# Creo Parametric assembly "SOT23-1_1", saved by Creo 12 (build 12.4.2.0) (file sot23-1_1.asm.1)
Units: Custom; MM, KILOGRAM, SECS

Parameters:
  PTC_WM_ITERATION = "0"
  PTC_WM_VERSION = "-.0"
  PTC_WM_LIFECYCLE_STATE = "In Work"
  PTC_WM_LIFECYCLE = "MO_CADDocument"
  PTC_WM_CREATED_BY = "Maximilian Roepper (Z0017RMS: MO)"
  PTC_WM_CREATED_ON = "18-Sep-26 11:36:42 AM"
  PTC_WM_MODIFIED_BY = "Maximilian Roepper (Z0017RMS: MO)"
  PTC_WM_MODIFIED_ON = "18-Sep-26 11:36:46 AM"
  PDMLINKNUMBER = "PDM000071455012"
  PTC_WM_NUMBER = "PDM000071455012"

Other parameters: WEIGHT, WEIGHT_FACTOR, WEIGHT_ADD, MC_ERRORS, SUPPLIER

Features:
  1. coordinate system
  2. imported feature
  3. component "SHAPESTRING278_1"
  4. component "PIN039_1"
  5. component "PIN038_1"
  6. component "PIN037_1"
  7. component "CASE001_1"

Other named items: DRW_VIEW_ORG, ROUGH-GROB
